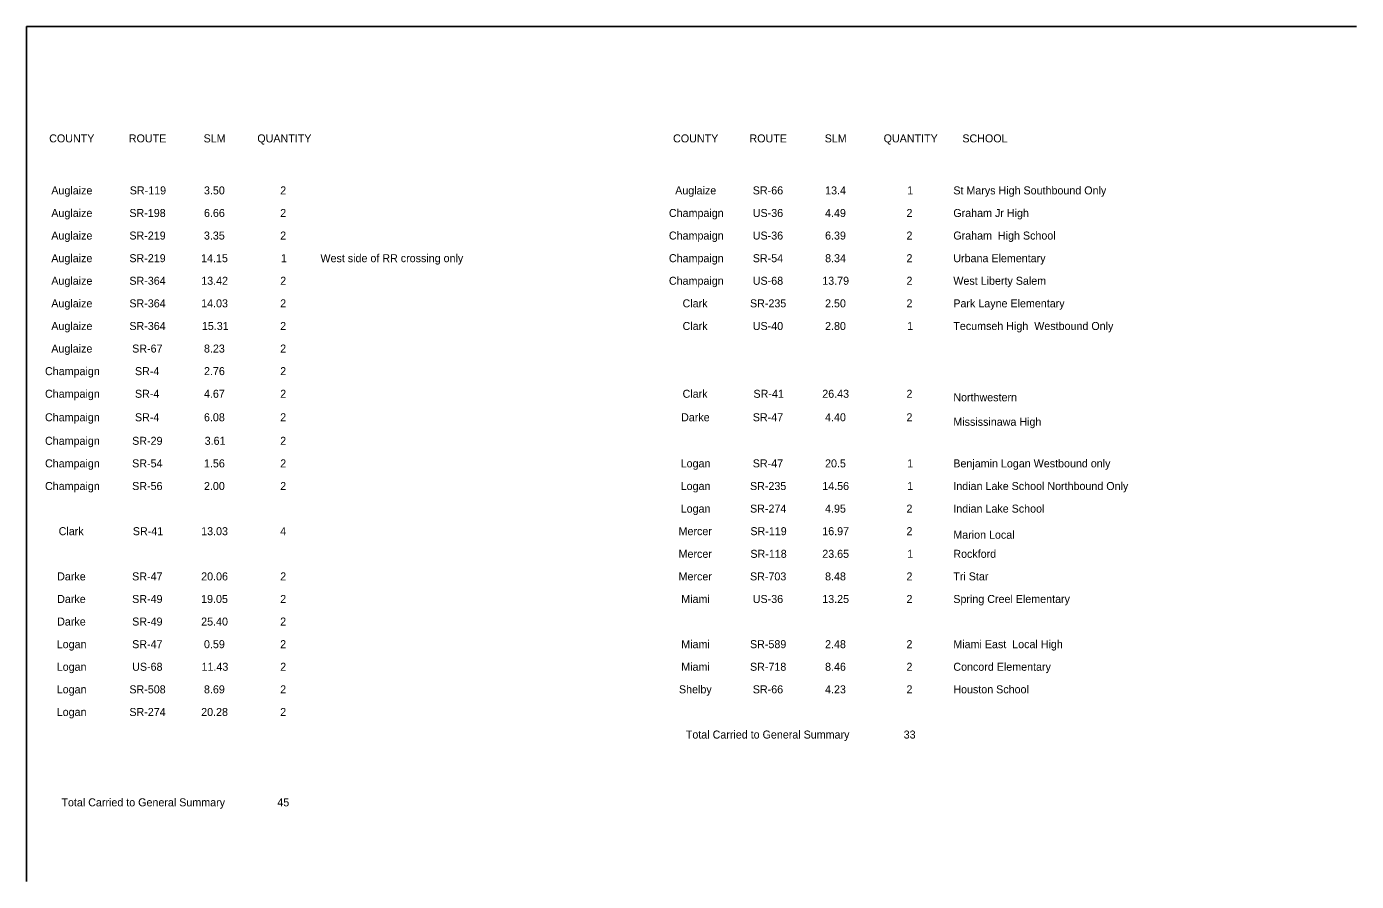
# Model space of a CAD drawing. Extents: x -27.4 to 34, y 0 to 22.
# Drawn here: x -27.35 to -4.1, y 6.54 to 21.5 of the extents above; entities that cross this region are included whole.
import ezdxf

# ---------------------------------------------------------------- set-up
doc = ezdxf.new("R2010")
doc.units = 0
doc.layers.add('SH_Data', color=7, linetype='Continuous')
doc.layers.add('SH_Text', color=7, linetype='Continuous')

msp = doc.modelspace()

# ---------------------------------------------------------------- linework, layer by layer
at = {"layer": 'SH_Data'}
for q in [(-4.097, 21.5), (-27.353, 6.545)]:
    msp.add_line((-27.353, 21.5), q, dxfattribs=at)

# ---------------------------------------------------------------- texts
at = {"layer": 'SH_Text'}
for s, p in [('COUNTY', (-26.958, 19.474)), ('ROUTE', (-25.565, 19.474)), ('SLM', (-24.258, 19.474)), ('QUANTITY', (-23.318, 19.474)), ('COUNTY', (-16.047, 19.474)), ('ROUTE', (-14.711, 19.474)), ('SLM', (-13.396, 19.474)), ('QUANTITY', (-12.365, 19.474)), ('SCHOOL', (-10.988, 19.474)), ('Auglaize', (-26.921, 18.564)), ('SR-119', (-25.549, 18.564)), ('3.50', (-24.251, 18.564)), ('2', (-22.918, 18.564)), ('Auglaize', (-16.01, 18.564)), ('SR-66', (-14.653, 18.564)), ('13.4', (-13.388, 18.564)), ('1', (-11.953, 18.564)), ('St Marys High Southbound Only', (-11.146, 18.564)), ('Auglaize', (-26.921, 18.169)), ('SR-198', (-25.556, 18.169)), ('6.66', (-24.251, 18.169)), ('2', (-22.918, 18.169)), ('Champaign', (-16.12, 18.169)), ('US-36', (-14.653, 18.169)), ('4.49', (-13.389, 18.169)), ('2', (-11.965, 18.169)), ('Graham Jr High', (-11.146, 18.169)), ('Auglaize', (-26.921, 17.774)), ('SR-219', (-25.556, 17.774)), ('3.35', (-24.252, 17.774)), ('2', (-22.918, 17.774)), ('Champaign', (-16.12, 17.774)), ('US-36', (-14.653, 17.774)), ('6.39', (-13.389, 17.774)), ('2', (-11.965, 17.774)), ('Graham  High School', (-11.146, 17.774)), ('Auglaize', (-26.921, 17.378)), ('SR-219', (-25.556, 17.378)), ('14.15', (-24.301, 17.378)), ('1', (-22.906, 17.378)), ('West side of RR crossing only', (-22.214, 17.378)), ('Champaign', (-16.12, 17.378)), ('SR-54', (-14.653, 17.378)), ('8.34', (-13.388, 17.378)), ('2', (-11.965, 17.378)), ('Urbana Elementary', (-11.146, 17.378)), ('Auglaize', (-26.921, 16.983)), ('SR-364', (-25.556, 16.983)), ('13.42', (-24.299, 16.983)), ('2', (-22.918, 16.983)), ('Champaign', (-16.12, 16.983)), ('US-68', (-14.653, 16.983)), ('13.79', (-13.438, 16.983)), ('2', (-11.965, 16.983)), ('West Liberty Salem', (-11.146, 16.983)), ('Auglaize', (-26.921, 16.588)), ('SR-364', (-25.556, 16.588)), ('14.03', (-24.3, 16.588)), ('2', (-22.918, 16.588)), ('Clark', (-15.881, 16.588)), ('SR-235', (-14.702, 16.588)), ('2.50', (-13.389, 16.588)), ('2', (-11.965, 16.588)), ('Park Layne Elementary', (-11.146, 16.588)), ('Auglaize', (-26.921, 16.192)), ('SR-364', (-25.556, 16.192)), ('15.31', (-24.288, 16.192)), ('2', (-22.918, 16.192)), ('Clark', (-15.881, 16.192)), ('US-40', (-14.653, 16.192)), ('2.80', (-13.389, 16.192)), ('1', (-11.953, 16.192)), ('Tecumseh High  Westbound Only', (-11.146, 16.192)), ('Auglaize', (-26.921, 15.797)), ('SR-67', (-25.507, 15.797)), ('8.23', (-24.251, 15.797)), ('2', (-22.918, 15.797)), ('Champaign', (-27.031, 15.402)), ('SR-4', (-25.458, 15.402)), ('2.76', (-24.251, 15.402)), ('2', (-22.918, 15.402)), ('Champaign', (-27.031, 15.006)), ('SR-4', (-25.458, 15.006)), ('4.67', (-24.251, 15.006)), ('2', (-22.918, 15.006)), ('Clark', (-15.881, 15.006)), ('SR-41', (-14.641, 15.006)), ('26.43', (-13.438, 15.006)), ('2', (-11.965, 15.006)), ('Northwestern', (-11.146, 14.945)), ('Champaign', (-27.031, 14.595)), ('SR-4', (-25.458, 14.595)), ('6.08', (-24.251, 14.595)), ('2', (-22.918, 14.595)), ('Darke', (-15.907, 14.595)), ('SR-47', (-14.653, 14.595)), ('4.40', (-13.389, 14.595)), ('2', (-11.965, 14.595)), ('Mississinawa High', (-11.146, 14.516)), ('Champaign', (-27.031, 14.183)), ('SR-29', (-25.507, 14.183)), ('3.61', (-24.239, 14.183)), ('2', (-22.918, 14.183)), ('Champaign', (-27.031, 13.788)), ('SR-54', (-25.507, 13.788)), ('1.56', (-24.251, 13.788)), ('2', (-22.918, 13.788)), ('Logan', (-15.914, 13.788)), ('SR-47', (-14.653, 13.788)), ('20.5', (-13.389, 13.788)), ('1', (-11.953, 13.788)), ('Benjamin Logan Westbound only', (-11.146, 13.788)), ('Champaign', (-27.031, 13.392)), ('SR-56', (-25.507, 13.392)), ('2.00', (-24.251, 13.392)), ('2', (-22.918, 13.392)), ('Logan', (-15.914, 13.392)), ('SR-235', (-14.702, 13.392)), ('14.56', (-13.438, 13.392)), ('1', (-11.953, 13.392)), ('Indian Lake School Northbound Only', (-11.146, 13.392)), ('Logan', (-15.914, 12.997)), ('SR-274', (-14.701, 12.997)), ('4.95', (-13.389, 12.997)), ('2', (-11.965, 12.997)), ('Indian Lake School', (-11.146, 12.997)), ('Clark', (-26.792, 12.602)), ('SR-41', (-25.495, 12.602)), ('13.03', (-24.3, 12.602)), ('4', (-22.918, 12.602)), ('Mercer', (-15.951, 12.602)), ('SR-119', (-14.695, 12.602)), ('16.97', (-13.438, 12.602)), ('2', (-11.965, 12.602)), ('Marion Local', (-11.146, 12.54)), ('Mercer', (-15.951, 12.206)), ('SR-118', (-14.695, 12.206)), ('23.65', (-13.438, 12.206)), ('1', (-11.953, 12.206)), ('Rockford', (-11.146, 12.206)), ('Darke', (-26.819, 11.811)), ('SR-47', (-25.507, 11.811)), ('20.06', (-24.3, 11.811)), ('2', (-22.918, 11.811)), ('Mercer', (-15.951, 11.811)), ('SR-703', (-14.702, 11.811)), ('8.48', (-13.389, 11.811)), ('2', (-11.965, 11.811)), ('Tri Star', (-11.146, 11.811)), ('Darke', (-26.819, 11.416)), ('SR-49', (-25.507, 11.416)), ('19.05', (-24.301, 11.416)), ('2', (-22.918, 11.416)), ('Miami', (-15.904, 11.416)), ('US-36', (-14.653, 11.416)), ('13.25', (-13.438, 11.416)), ('2', (-11.965, 11.416)), ('Spring Creel Elementary', (-11.146, 11.416)), ('Darke', (-26.819, 11.021)), ('SR-49', (-25.507, 11.021)), ('25.40', (-24.3, 11.021)), ('2', (-22.918, 11.021)), ('Logan', (-26.826, 10.625)), ('SR-47', (-25.507, 10.625)), ('0.59', (-24.251, 10.625)), ('2', (-22.918, 10.625)), ('Miami', (-15.904, 10.625)), ('SR-589', (-14.702, 10.625)), ('2.48', (-13.389, 10.625)), ('2', (-11.965, 10.625)), ('Miami East  Local High', (-11.146, 10.625)), ('Logan', (-26.826, 10.23)), ('US-68', (-25.507, 10.23)), ('11.43', (-24.294, 10.23)), ('2', (-22.918, 10.23)), ('Miami', (-15.904, 10.23)), ('SR-718', (-14.702, 10.23)), ('8.46', (-13.389, 10.23)), ('2', (-11.965, 10.23)), ('Concord Elementary', (-11.146, 10.23)), ('Logan', (-26.826, 9.835)), ('SR-508', (-25.556, 9.835)), ('8.69', (-24.251, 9.835)), ('2', (-22.918, 9.835)), ('Shelby', (-15.944, 9.835)), ('SR-66', (-14.653, 9.835)), ('4.23', (-13.389, 9.835)), ('2', (-11.965, 9.835)), ('Houston School', (-11.146, 9.835)), ('Logan', (-26.826, 9.439)), ('SR-274', (-25.556, 9.439)), ('20.28', (-24.3, 9.439)), ('2', (-22.918, 9.439)), ('Total Carried to General Summary', (-15.824, 9.044)), ('33', (-12.014, 9.044)), ('Total Carried to General Summary', (-26.744, 7.858)), ('45', (-22.968, 7.858))]:
    msp.add_text(s, height=0.14, dxfattribs=at).set_placement(p)

doc.saveas('drawing.dxf')
